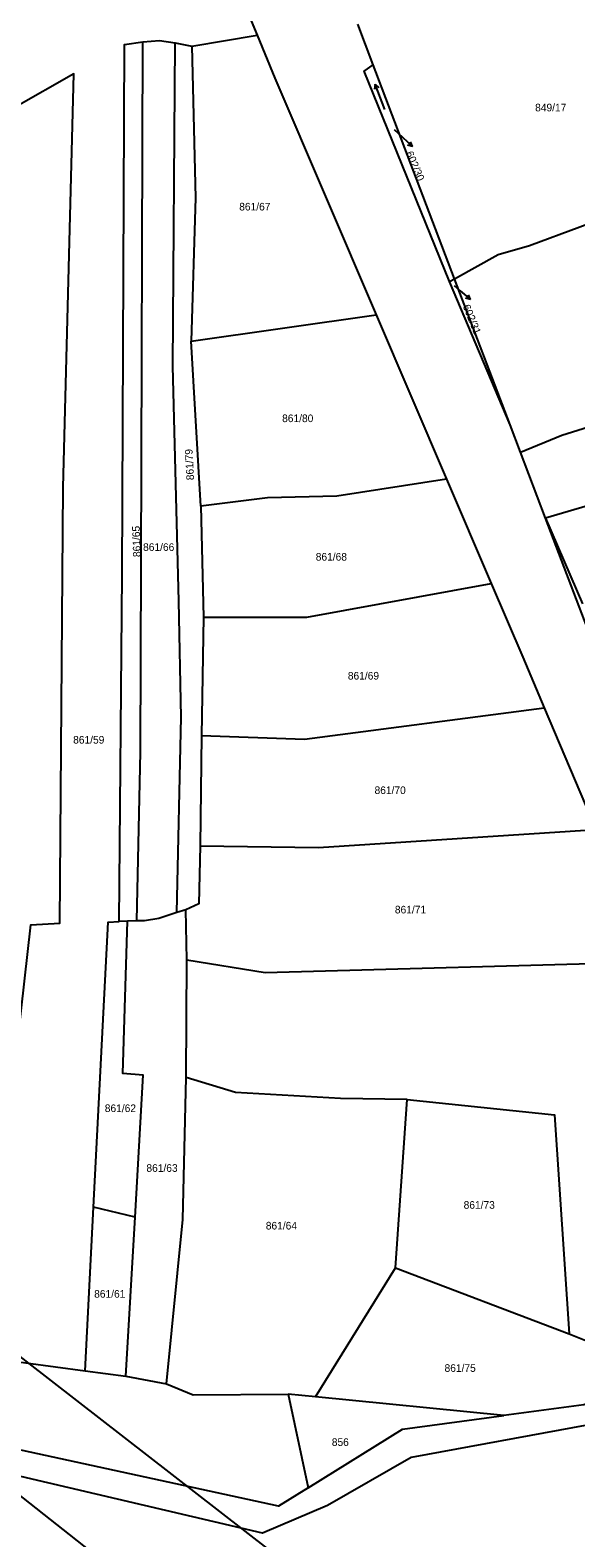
# Model space of a CAD drawing. Extents: x -757266 to -753360, y -1162585 to -1157740.
# Drawn here: x -756866.4 to -756744.8, y -1160185.6 to -1159849.8 of the extents above; entities that cross this region are included whole.
import ezdxf

# ---------------------------------------------------------------- set-up
doc = ezdxf.new("R2010")
doc.units = 0
for name, color, linetype in [('Hranice parcel', 7, 'Continuous'), ('Parcelní čísla', 7, 'Continuous'), ('Pop  PČ popisy', 7, 'Continuous'), ('Poz předměty', 7, 'Continuous'), ('Značky kultur', 7, 'Continuous')]:
    doc.layers.add(name, color=color, linetype=linetype)

msp = doc.modelspace()

# ---------------------------------------------------------------- linework, layer by layer
at = {"layer": 'Hranice parcel'}
for p, q in [((-756836.29, -1159801.39), (-756815.78, -1159850.98)), ((-756789.91, -1159857.57), (-756793.35, -1159848.53)), ((-756834.04, -1159852.67), (-756830.38, -1159853.4)), ((-756830.38, -1159853.4), (-756815.78, -1159850.98)), ((-756771.8, -1159905.2), (-756789.91, -1159857.57)), ((-756772.92, -1159905.83), (-756771.8, -1159905.2)), ((-756759.44, -1159937.7), (-756772.92, -1159905.83)), ((-756759.44, -1159937.7), (-756771.8, -1159905.2)), ((-756830.48, -1159919.13), (-756789.27, -1159913.2)), ((-756789.27, -1159913.2), (-756773.58, -1159949.84)), ((-756828.31, -1159955.86), (-756830.48, -1159919.13)), ((-756757.11, -1159943.81), (-756759.44, -1159937.7)), ((-756751.53, -1159958.49), (-756757.11, -1159943.81)), ((-756703.29, -1159944.31), (-756751.53, -1159958.49)), ((-756773.58, -1159949.84), (-756763.64, -1159973.05)), ((-756828.31, -1159955.86), (-756827.75, -1159980.55)), ((-756751.53, -1159958.49), (-756743.32, -1159977.59)), ((-756827.75, -1159980.55), (-756828.16, -1160006.9)), ((-756751.84, -1160000.73), (-756740.37, -1160027.84)), ((-756828.16, -1160006.9), (-756828.48, -1160031.46)), ((-756831.67, -1160045.74), (-756833.72, -1160046.36)), ((-756831.5, -1160056.84), (-756831.67, -1160045.74)), ((-756844.68, -1160048.28), (-756846.52, -1160048.32)), ((-756842.59, -1160048.16), (-756844.68, -1160048.28)), ((-756831.64, -1160083.08), (-756831.5, -1160056.84)), ((-756784.96, -1160125.47), (-756782.37, -1160088)), ((-756854.12, -1160148.42), (-756852.26, -1160111.93)), ((-756843.01, -1160114.16), (-756852.26, -1160111.93)), ((-756845.02, -1160149.57), (-756843.01, -1160114.16)), ((-756802.78, -1160154.19), (-756784.96, -1160125.47)), ((-756784.96, -1160125.47), (-756746.25, -1160140.14)), ((-756875.38, -1160145.5), (-756854.12, -1160148.42)), ((-756854.12, -1160148.42), (-756845.02, -1160149.57)), ((-756845.02, -1160149.57), (-756835.97, -1160151.28)), ((-756802.78, -1160154.19), (-756808.85, -1160153.59)), ((-756808.85, -1160153.59), (-756804.41, -1160174.44)), ((-756760.87, -1160158.35), (-756802.78, -1160154.19))]:
    msp.add_line(p, q, dxfattribs=at)
for points in [[(-756846.52, -1160048.32), (-756845.88, -1159971.15), (-756845.38, -1159853.03), (-756841.23, -1159852.42)], [(-756842.59, -1160048.16), (-756841.82, -1160010.57), (-756841.61, -1159968.84), (-756841.23, -1159852.42)], [(-756841.23, -1159852.42), (-756837.57, -1159852.18), (-756834.04, -1159852.67)], [(-756833.72, -1160046.36), (-756832.74, -1160002.86), (-756833.26, -1159977.02), (-756834.57, -1159924.64), (-756834.04, -1159852.67)], [(-756815.78, -1159850.98), (-756811.83, -1159860.53), (-756789.27, -1159913.2)], [(-756830.38, -1159853.4), (-756829.5, -1159887.2), (-756830.48, -1159919.13)], [(-756875.38, -1160145.5), (-756870.45, -1160086.68), (-756866.24, -1160049.08), (-756859.74, -1160048.67), (-756859.01, -1159951.71), (-756856.62, -1159859.56), (-756869.93, -1159867.13)], [(-756772.92, -1159905.83), (-756791.98, -1159858.95), (-756789.91, -1159857.57)], [(-756771.8, -1159905.2), (-756762.09, -1159899.78), (-756755.13, -1159897.79), (-756732.65, -1159889.49), (-756713.32, -1159884.66)], [(-756757.11, -1159943.81), (-756747.92, -1159940.02), (-756738.18, -1159936.97), (-756706, -1159926.11)], [(-756773.58, -1159949.84), (-756798.05, -1159953.61), (-756813.52, -1159954), (-756828.31, -1159955.86)], [(-756710.89, -1160056.79), (-756741.66, -1159984.45), (-756751.53, -1159958.49)], [(-756827.75, -1159980.55), (-756804.74, -1159980.55), (-756763.64, -1159973.05)], [(-756763.64, -1159973.05), (-756756.59, -1159989.49), (-756751.84, -1160000.73)], [(-756828.16, -1160006.9), (-756805.24, -1160007.72), (-756751.84, -1160000.73)], [(-756828.48, -1160031.46), (-756802.13, -1160031.83), (-756740.37, -1160027.84)], [(-756828.48, -1160031.46), (-756828.8, -1160044.41), (-756831.67, -1160045.74)], [(-756833.72, -1160046.36), (-756837.7, -1160047.68), (-756840.86, -1160048.19), (-756842.59, -1160048.16)], [(-756852.26, -1160111.93), (-756848.98, -1160048.49), (-756846.52, -1160048.32)], [(-756843.01, -1160114.16), (-756841.2, -1160082.57), (-756845.72, -1160082.17), (-756844.68, -1160048.28)], [(-756831.5, -1160056.84), (-756814.04, -1160059.7), (-756727.91, -1160057.32)], [(-756835.97, -1160151.28), (-756832.35, -1160114.66), (-756831.64, -1160083.08)], [(-756782.37, -1160088), (-756797.26, -1160087.77), (-756820.61, -1160086.42), (-756831.64, -1160083.08)], [(-756782.37, -1160088), (-756749.52, -1160091.38), (-756746.25, -1160140.14)], [(-756804.41, -1160174.44), (-756811.01, -1160178.54), (-756894.48, -1160160.39), (-756987.32, -1160141.97), (-757044.84, -1160119.83), (-757060.6, -1160113.6), (-757067.17, -1160113.38)], [(-756746.25, -1160140.14), (-756736.24, -1160144.19), (-756729.3, -1160151.42)], [(-756835.97, -1160151.28), (-756830.03, -1160153.75), (-756808.85, -1160153.59)], [(-756729.3, -1160151.42), (-756742.99, -1160155.96), (-756760.87, -1160158.35)], [(-756716.37, -1160153.06), (-756741.86, -1160160.44), (-756781.48, -1160167.69), (-756800.11, -1160178.39), (-756814.59, -1160184.55), (-756894.79, -1160165.77), (-756983.16, -1160153.27)], [(-756804.41, -1160174.44), (-756783.39, -1160161.37), (-756760.87, -1160158.35)]]:
    msp.add_lwpolyline(points, dxfattribs=at)
at = {"layer": 'Pop  PČ popisy'}
for p, q in [((-756785.28, -1159871.94), (-756783.4, -1159873.71)), ((-756783.4, -1159873.71), (-756781.205, -1159875.757)), ((-756781.205, -1159875.757), (-756782.279, -1159875.44)), ((-756781.205, -1159875.757), (-756781.596, -1159874.707)), ((-756771.93, -1159906.72), (-756770.58, -1159907.87)), ((-756770.58, -1159907.87), (-756768.281, -1159909.799)), ((-756768.281, -1159909.799), (-756769.37, -1159909.539)), ((-756768.281, -1159909.799), (-756768.726, -1159908.772))]:
    msp.add_line(p, q, dxfattribs=at)
at = {"layer": 'Poz předměty'}
for p, q in [((-756807.88, -1160192.32), (-756872.24, -1160142.38)), ((-756874.39, -1160171.69), (-756683.22, -1160322.27))]:
    msp.add_line(p, q, dxfattribs=at)
at = {"layer": 'Značky kultur'}
for p, q in [((-756789.503, -1159861.9), (-756789.621, -1159862.992)), ((-756787.353, -1159867.502), (-756789.503, -1159861.9)), ((-756789.503, -1159861.9), (-756788.685, -1159862.633))]:
    msp.add_line(p, q, dxfattribs=at)

# ---------------------------------------------------------------- texts
at = {"layer": 'Parcelní čísla'}
for s, p in [('849/17', (-756753.86, -1159867.93)), ('861/67', (-756819.79, -1159890)), ('861/80', (-756810.23, -1159937.13)), ('861/66', (-756841.21, -1159965.81)), ('861/68', (-756802.74, -1159967.97)), ('861/69', (-756795.59, -1159994.46)), ('861/59', (-756856.79, -1160008.72)), ('861/70', (-756789.64, -1160019.95)), ('861/71', (-756785.11, -1160046.54)), ('861/62', (-756849.74, -1160090.77)), ('861/63', (-756840.47, -1160104.08)), ('861/73', (-756769.79, -1160112.3)), ('861/64', (-756813.87, -1160116.92)), ('861/61', (-756852.11, -1160132.1)), ('861/75', (-756774.04, -1160148.62)), ('856', (-756799.16, -1160165.12))]:
    msp.add_text(s, height=1.7, dxfattribs=at).set_placement(p)
for s, rotation, p in [('602/30', 293, (-756782.722, -1159877.213)), ('602/31', 292, (-756770.021, -1159911.327)), ('861/79', 92.999997, (-756829.851, -1159950.015)), ('861/65', 92, (-756841.73, -1159967.15))]:
    msp.add_text(s, height=1.7, rotation=rotation, dxfattribs=at).set_placement(p)

doc.saveas('drawing.dxf')
